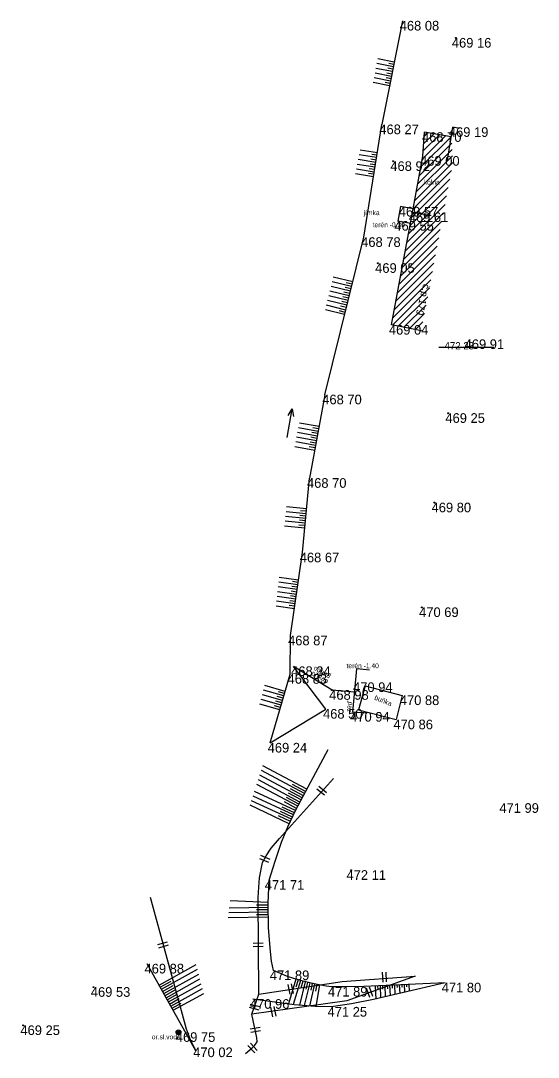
# Model space of a CAD drawing. Extents: x -553731 to -553573, y -1076100 to -1075378.
# Drawn here: x -553641.9 to -553588.3, y -1075774 to -1075666.6 of the extents above; entities that cross this region are included whole.
import ezdxf

# ---------------------------------------------------------------- set-up
doc = ezdxf.new("R2010")
doc.units = 0
for name, color, linetype in [('1', 7, 'Continuous'), ('14', 7, 'Continuous'), ('18', 7, 'Continuous'), ('26', 7, 'Continuous'), ('27', 7, 'Continuous'), ('28', 7, 'Continuous'), ('32', 7, 'Continuous'), ('52', 7, 'Continuous'), ('54_C_POPISNA', 7, 'Continuous'), ('6', 7, 'Continuous'), ('62', 7, 'Continuous')]:
    doc.layers.add(name, color=color, linetype=linetype)

# ---------------------------------------------------------------- blocks, each defined once
blk = doc.blocks.new('POINT_DISPLAY')
blk.add_line((0, 0), (0, 0))
blk = doc.blocks.new('T')
at = {"layer": '6'}
blk.add_circle((0, 0), 0.05, dxfattribs=at)
blk = doc.blocks.new('VOTOK')
at = {"layer": '28'}
for p, q in [((-3.001, 0.001), (0, 0)), ((-0.751, 0.282), (0, 0)), ((0, 0), (-0.751, -0.281))]:
    blk.add_line(p, q, dxfattribs=at)
blk = doc.blocks.new('ROV')
at = {"layer": '62'}
for p, q in [((-0.348, -0.51), (-0.348, 0.51)), ((0, -0.51), (0, 0.51))]:
    blk.add_line(p, q, dxfattribs=at)
blk = doc.blocks.new('OSV')
at = {"layer": '1'}
for radius in [0.25, 0.158, 0.05]:
    blk.add_circle((0, 0), radius, dxfattribs=at)

msp = doc.modelspace()

# ---------------------------------------------------------------- linework, layer by layer
at = {"layer": '14'}
for p, q in [((-553600.25, -1075680.66), (-553600.07, -1075678.19)), ((-553597.31, -1075678.65), (-553600.07, -1075678.19)), ((-553597.71, -1075681.08), (-553597.15, -1075677.67)), ((-553596.45, -1075677.79), (-553597.15, -1075677.67)), ((-553601.31, -1075686.49), (-553600.25, -1075680.66)), ((-553603.49, -1075698.16), (-553601.31, -1075686.49)), ((-553599.38, -1075686.85), (-553601.31, -1075686.49)), ((-553600.41, -1075698.75), (-553603.49, -1075698.16))]:
    msp.add_line(p, q, dxfattribs=at)
at = {"layer": '18'}
for p, q in [((-553602.57, -1075685.9), (-553602.85, -1075687.4)), ((-553601.25, -1075686.14), (-553602.57, -1075685.9)), ((-553601.53, -1075687.65), (-553602.85, -1075687.4)), ((-553607.52, -1075738.26), (-553607.08, -1075733.8)), ((-553605.79, -1075733.92), (-553607.08, -1075733.8)), ((-553606.24, -1075735.54), (-553606.9, -1075738.05)), ((-553606.24, -1075735.54), (-553602.38, -1075736.54)), ((-553602.38, -1075736.54), (-553603.03, -1075739.05)), ((-553606.15, -1075738.39), (-553607.52, -1075738.26)), ((-553606.9, -1075738.05), (-553603.03, -1075739.05))]:
    msp.add_line(p, q, dxfattribs=at)
at = {"layer": '26'}
for p, q in [((-553603.22, -1075670.93), (-553604.92, -1075670.59)), ((-553603.41, -1075671.91), (-553605.11, -1075671.58)), ((-553603.31, -1075671.42), (-553605.01, -1075671.08)), ((-553603.36, -1075671.67), (-553603.87, -1075671.56)), ((-553603.26, -1075671.18), (-553603.77, -1075671.07)), ((-553603.6, -1075672.89), (-553605.3, -1075672.56)), ((-553603.51, -1075672.4), (-553605.2, -1075672.07)), ((-553603.55, -1075672.65), (-553604.06, -1075672.55)), ((-553603.46, -1075672.16), (-553603.97, -1075672.06)), ((-553603.7, -1075673.38), (-553605.4, -1075673.05)), ((-553603.65, -1075673.14), (-553604.16, -1075673.04)), ((-553604.96, -1075680.33), (-553606.76, -1075680.04)), ((-553605.12, -1075681.32), (-553606.95, -1075681.02)), ((-553605.04, -1075680.82), (-553606.85, -1075680.53)), ((-553605.08, -1075681.07), (-553605.63, -1075680.98)), ((-553605, -1075680.58), (-553605.54, -1075680.49)), ((-553605.36, -1075682.8), (-553607.24, -1075682.5)), ((-553605.28, -1075682.31), (-553607.14, -1075682.01)), ((-553605.2, -1075681.81), (-553607.05, -1075681.52)), ((-553605.32, -1075682.55), (-553605.88, -1075682.46)), ((-553605.24, -1075682.06), (-553605.8, -1075681.97)), ((-553605.16, -1075681.56), (-553605.71, -1075681.48)), ((-553607.51, -1075693.69), (-553609.53, -1075693.2)), ((-553607.75, -1075694.67), (-553609.76, -1075694.17)), ((-553607.63, -1075694.18), (-553609.64, -1075693.68)), ((-553607.69, -1075694.42), (-553608.3, -1075694.27)), ((-553607.57, -1075693.94), (-553608.18, -1075693.79)), ((-553607.99, -1075695.64), (-553610, -1075695.14)), ((-553607.87, -1075695.15), (-553609.88, -1075694.65)), ((-553607.93, -1075695.39), (-553608.53, -1075695.24)), ((-553607.81, -1075694.91), (-553608.42, -1075694.76)), ((-553608.23, -1075696.61), (-553610.23, -1075696.11)), ((-553608.11, -1075696.12), (-553610.12, -1075695.63)), ((-553608.17, -1075696.36), (-553608.77, -1075696.22)), ((-553608.05, -1075695.88), (-553608.65, -1075695.73)), ((-553608.35, -1075697.09), (-553610.35, -1075696.6)), ((-553608.29, -1075696.85), (-553608.89, -1075696.7)), ((-553611.18, -1075709.67), (-553613.22, -1075709.3)), ((-553611.09, -1075709.18), (-553613.12, -1075708.81)), ((-553611, -1075708.69), (-553613.03, -1075708.32)), ((-553611.14, -1075709.42), (-553611.75, -1075709.31)), ((-553611.05, -1075708.93), (-553611.66, -1075708.82)), ((-553611.36, -1075710.65), (-553613.41, -1075710.28)), ((-553611.27, -1075710.16), (-553613.32, -1075709.79)), ((-553611.32, -1075710.41), (-553611.93, -1075710.3)), ((-553611.23, -1075709.92), (-553611.84, -1075709.8)), ((-553611.45, -1075711.15), (-553613.51, -1075710.77)), ((-553611.41, -1075710.9), (-553612.02, -1075710.79)), ((-553612.33, -1075717.71), (-553614.41, -1075717.51)), ((-553612.29, -1075717.21), (-553614.36, -1075717.01)), ((-553612.36, -1075717.96), (-553612.98, -1075717.9)), ((-553612.31, -1075717.46), (-553612.93, -1075717.4)), ((-553612.47, -1075719.2), (-553614.57, -1075719)), ((-553612.43, -1075718.7), (-553614.52, -1075718.5)), ((-553612.38, -1075718.2), (-553614.47, -1075718)), ((-553612.45, -1075718.95), (-553613.08, -1075718.89)), ((-553612.4, -1075718.45), (-553613.03, -1075718.39)), ((-553613.12, -1075724.59), (-553615.13, -1075724.31)), ((-553613.26, -1075725.58), (-553615.23, -1075725.3)), ((-553613.19, -1075725.08), (-553615.18, -1075724.8)), ((-553613.23, -1075725.33), (-553613.82, -1075725.25)), ((-553613.16, -1075724.84), (-553613.76, -1075724.75)), ((-553613.4, -1075726.57), (-553615.34, -1075726.3)), ((-553613.33, -1075726.07), (-553615.29, -1075725.8)), ((-553613.37, -1075726.32), (-553613.95, -1075726.24)), ((-553613.3, -1075725.83), (-553613.89, -1075725.74)), ((-553613.54, -1075727.56), (-553615.44, -1075727.29)), ((-553613.47, -1075727.06), (-553615.39, -1075726.79)), ((-553613.51, -1075727.31), (-553614.08, -1075727.23)), ((-553613.44, -1075726.82), (-553614.02, -1075726.74)), ((-553614.65, -1075736.6), (-553616.74, -1075735.99)), ((-553614.51, -1075736.12), (-553616.6, -1075735.51)), ((-553614.58, -1075736.36), (-553615.2, -1075736.18)), ((-553614.92, -1075737.56), (-553617.01, -1075736.96)), ((-553614.78, -1075737.08), (-553616.87, -1075736.48)), ((-553614.85, -1075737.32), (-553615.48, -1075737.14)), ((-553614.72, -1075736.84), (-553615.34, -1075736.66)), ((-553615.06, -1075738.04), (-553617.14, -1075737.44)), ((-553614.99, -1075737.8), (-553615.62, -1075737.62)), ((-553612.74, -1075747.15), (-553617.13, -1075744.81)), ((-553612.51, -1075746.71), (-553616.97, -1075744.33)), ((-553612.27, -1075746.26), (-553616.82, -1075743.84)), ((-553613.21, -1075748.03), (-553617.44, -1075745.78)), ((-553612.98, -1075747.59), (-553617.28, -1075745.3)), ((-553612.39, -1075746.49), (-553613.74, -1075745.77)), ((-553613.44, -1075748.47), (-553617.67, -1075746.49)), ((-553612.86, -1075747.37), (-553614.16, -1075746.67)), ((-553612.62, -1075746.93), (-553613.95, -1075746.22)), ((-553614.08, -1075749.83), (-553618.13, -1075747.93)), ((-553613.87, -1075749.38), (-553617.98, -1075747.45)), ((-553613.66, -1075748.93), (-553617.82, -1075746.97)), ((-553613.33, -1075748.25), (-553614.59, -1075747.58)), ((-553613.09, -1075747.81), (-553614.37, -1075747.13)), ((-553613.97, -1075749.6), (-553615.2, -1075749.03)), ((-553613.76, -1075749.15), (-553615, -1075748.57)), ((-553613.55, -1075748.7), (-553614.81, -1075748.11)), ((-553616.25, -1075758.51), (-553620.3, -1075758.57)), ((-553616.26, -1075758.01), (-553620.22, -1075757.82)), ((-553616.25, -1075758.76), (-553617.47, -1075758.77)), ((-553616.26, -1075758.26), (-553617.46, -1075758.27)), ((-553616.24, -1075759.51), (-553620.4, -1075759.57)), ((-553616.24, -1075759.01), (-553620.35, -1075759.07)), ((-553616.24, -1075759.26), (-553617.48, -1075759.28)), ((-553627.56, -1075766.55), (-553623.73, -1075764.42)), ((-553627.32, -1075766.99), (-553623.59, -1075764.92)), ((-553627.44, -1075766.77), (-553626.31, -1075766.14)), ((-553627.07, -1075767.43), (-553623.46, -1075765.42)), ((-553626.83, -1075767.86), (-553623.33, -1075765.92)), ((-553613.4, -1075765.93), (-553614.17, -1075768.51)), ((-553612.92, -1075766.07), (-553613.67, -1075768.58)), ((-553613.16, -1075766), (-553613.39, -1075766.77)), ((-553612.44, -1075766.21), (-553613.04, -1075768.64)), ((-553612.68, -1075766.15), (-553612.9, -1075766.88)), ((-553612.19, -1075766.27), (-553612.37, -1075766.99)), ((-553627.2, -1075767.21), (-553626.1, -1075766.6)), ((-553626.95, -1075767.64), (-553625.89, -1075767.05)), ((-553626.59, -1075768.3), (-553623.2, -1075766.42)), ((-553626.35, -1075768.74), (-553623.07, -1075766.92)), ((-553611.95, -1075766.33), (-553612.54, -1075768.68)), ((-553611.46, -1075766.44), (-553611.98, -1075768.73)), ((-553611.71, -1075766.39), (-553611.86, -1075767.08)), ((-553611.22, -1075766.5), (-553611.37, -1075767.17)), ((-553610.97, -1075766.54), (-553611.34, -1075768.78)), ((-553605.19, -1075766.65), (-553605.12, -1075768)), ((-553604.94, -1075766.64), (-553604.92, -1075767.03)), ((-553604.69, -1075766.62), (-553604.63, -1075767.88)), ((-553604.44, -1075766.61), (-553604.42, -1075766.98)), ((-553604.19, -1075766.6), (-553604.14, -1075767.77)), ((-553603.94, -1075766.59), (-553603.92, -1075766.93)), ((-553603.69, -1075766.58), (-553603.64, -1075767.65)), ((-553603.44, -1075766.57), (-553603.43, -1075766.88)), ((-553603.19, -1075766.56), (-553603.14, -1075767.54)), ((-553602.94, -1075766.54), (-553602.93, -1075766.82)), ((-553602.69, -1075766.53), (-553602.65, -1075767.42)), ((-553602.44, -1075766.52), (-553602.43, -1075766.77)), ((-553602.19, -1075766.51), (-553602.15, -1075767.3)), ((-553601.94, -1075766.5), (-553601.93, -1075766.72)), ((-553601.69, -1075766.49), (-553601.66, -1075767.19)), ((-553626.71, -1075768.08), (-553625.68, -1075767.51)), ((-553626.47, -1075768.52), (-553625.47, -1075767.96)), ((-553626.22, -1075768.96), (-553625.26, -1075768.42)), ((-553626.1, -1075769.17), (-553622.94, -1075767.42))]:
    msp.add_line(p, q, dxfattribs=at)
at = {"layer": '27'}
for p, q in [((-553602.37, -1075666.65), (-553604.49, -1075677.39)), ((-553606.37, -1075689.07), (-553604.49, -1075677.39)), ((-553610.4, -1075705.38), (-553606.37, -1075689.07)), ((-553610.4, -1075705.38), (-553611.98, -1075714.03)), ((-553612.72, -1075721.75), (-553611.98, -1075714.03)), ((-553613.94, -1075730.35), (-553612.72, -1075721.75)), ((-553613.99, -1075734.33), (-553613.94, -1075730.35)), ((-553610.31, -1075737.95), (-553613.63, -1075733.53)), ((-553609.66, -1075735.99), (-553613.63, -1075733.53)), ((-553616.05, -1075741.46), (-553613.99, -1075734.33)), ((-553607.32, -1075736.22), (-553609.66, -1075735.99)), ((-553616.05, -1075741.46), (-553610.31, -1075737.95)), ((-553623.77, -1075773.38), (-553628.78, -1075764.35))]:
    msp.add_line(p, q, dxfattribs=at)
for points in [[(-553616.15, -1075755.68), (-553615.56, -1075753.71), (-553614.89, -1075751.75), (-553614.24, -1075750.17), (-553613.4, -1075748.38), (-553610.07, -1075742.13)], [(-553615.72, -1075765.04), (-553615.92, -1075764.09), (-553616.04, -1075763.09), (-553616.22, -1075760.63), (-553616.26, -1075758.07), (-553616.15, -1075755.68)], [(-553609.7, -1075766.74), (-553610.28, -1075766.65), (-553611.15, -1075766.51), (-553611.8, -1075766.36), (-553612.66, -1075766.15), (-553613.62, -1075765.86), (-553614.28, -1075765.65), (-553615.72, -1075765.04)], [(-553597.93, -1075766.31), (-553605.36, -1075768.06), (-553607.63, -1075768.5), (-553609.75, -1075768.82)], [(-553597.93, -1075766.31), (-553606.36, -1075766.7), (-553608.37, -1075766.75), (-553609.7, -1075766.74)], [(-553609.75, -1075768.82), (-553611.4, -1075768.77), (-553613.57, -1075768.59), (-553617.87, -1075768.01)]]:
    msp.add_lwpolyline(points, dxfattribs=at)
at = {"layer": '32'}
for p, q in [((-553600.46, -1075681.79), (-553597.31, -1075678.65)), ((-553600.3, -1075680.93), (-553597.92, -1075678.55)), ((-553600.21, -1075680.13), (-553598.53, -1075678.45)), ((-553600.16, -1075679.37), (-553599.13, -1075678.34)), ((-553600.1, -1075678.61), (-553599.74, -1075678.25)), ((-553600.77, -1075683.52), (-553597.23, -1075679.98)), ((-553600.61, -1075682.66), (-553597.27, -1075679.31)), ((-553601.08, -1075685.25), (-553597.15, -1075681.31)), ((-553600.93, -1075684.38), (-553597.19, -1075680.64)), ((-553601.24, -1075686.11), (-553597.3, -1075682.17)), ((-553601.4, -1075686.98), (-553597.46, -1075683.04)), ((-553601.56, -1075687.85), (-553597.63, -1075683.91)), ((-553601.89, -1075689.59), (-553597.96, -1075685.66)), ((-553601.73, -1075688.72), (-553597.79, -1075684.78)), ((-553602.05, -1075690.46), (-553598.12, -1075686.53)), ((-553602.21, -1075691.33), (-553598.28, -1075687.4)), ((-553602.38, -1075692.2), (-553598.45, -1075688.27)), ((-553602.7, -1075693.94), (-553598.77, -1075690.01)), ((-553602.54, -1075693.07), (-553598.61, -1075689.14)), ((-553602.86, -1075694.81), (-553598.94, -1075690.88)), ((-553603.03, -1075695.67), (-553599.1, -1075691.75)), ((-553603.19, -1075696.54), (-553599.26, -1075692.62)), ((-553603.35, -1075697.41), (-553599.43, -1075693.49)), ((-553603.41, -1075698.18), (-553599.59, -1075694.36)), ((-553602.81, -1075698.29), (-553599.75, -1075695.23)), ((-553602.22, -1075698.4), (-553599.92, -1075696.1)), ((-553601.62, -1075698.52), (-553600.08, -1075696.97)), ((-553601.03, -1075698.63), (-553600.24, -1075697.84)), ((-553600.44, -1075698.74), (-553600.41, -1075698.71))]:
    msp.add_line(p, q, dxfattribs=at)
at = {"layer": '62'}
for p, q in [((-553598.61, -1075700.47), (-553592.92, -1075700.47)), ((-553615.1, -1075751.35), (-553609.5, -1075745.14)), ((-553615.95, -1075752.38), (-553615.1, -1075751.35)), ((-553616.84, -1075753.87), (-553616.46, -1075753.17)), ((-553616.46, -1075753.17), (-553615.95, -1075752.38)), ((-553617.16, -1075755.44), (-553616.84, -1075753.87)), ((-553617.24, -1075756.4), (-553617.16, -1075755.44)), ((-553617.3, -1075757.5), (-553617.24, -1075756.4)), ((-553624.72, -1075771.13), (-553628.45, -1075757.49)), ((-553617.25, -1075767.5), (-553617.3, -1075757.5)), ((-553617.25, -1075767.5), (-553608.6, -1075766.2)), ((-553608.6, -1075766.2), (-553601.05, -1075765.62)), ((-553601.05, -1075765.62), (-553608.12, -1075768.18)), ((-553617.95, -1075769.56), (-553617.25, -1075767.5)), ((-553608.12, -1075768.18), (-553617.95, -1075769.56)), ((-553617.44, -1075772.03), (-553617.95, -1075769.56)), ((-553624.32, -1075772.24), (-553624.72, -1075771.13)), ((-553623.77, -1075773.38), (-553624.32, -1075772.24)), ((-553617.64, -1075772.78), (-553617.4, -1075772.45)), ((-553617.4, -1075772.45), (-553617.44, -1075772.03)), ((-553618.6, -1075773.63), (-553617.91, -1075773.06)), ((-553617.91, -1075773.06), (-553617.64, -1075772.78))]:
    msp.add_line(p, q, dxfattribs=at)

# ---------------------------------------------------------------- block references
at = {"layer": '1'}
for name, p in [('POINT_DISPLAY', (-553602.37, -1075666.65)), ('POINT_DISPLAY', (-553596.84, -1075668.42)), ('POINT_DISPLAY', (-553604.49, -1075677.39)), ('POINT_DISPLAY', (-553600.07, -1075678.19)), ('POINT_DISPLAY', (-553597.15, -1075677.67)), ('POINT_DISPLAY', (-553603.33, -1075681.2)), ('POINT_DISPLAY', (-553600.25, -1075680.66)), ('POINT_DISPLAY', (-553602.47, -1075685.92)), ('POINT_DISPLAY', (-553601.31, -1075686.49)), ('POINT_DISPLAY', (-553602.92, -1075687.39)), ('POINT_DISPLAY', (-553606.37, -1075689.07)), ('POINT_DISPLAY', (-553604.9, -1075691.76)), ('POINT_DISPLAY', (-553603.49, -1075698.16)), ('POINT_DISPLAY', (-553595.53, -1075699.65)), ('POINT_DISPLAY', (-553610.4, -1075705.38)), ('POINT_DISPLAY', (-553597.63, -1075707.3)), ('POINT_DISPLAY', (-553611.98, -1075714.03)), ('POINT_DISPLAY', (-553599.06, -1075716.57)), ('POINT_DISPLAY', (-553612.72, -1075721.75)), ('POINT_DISPLAY', (-553600.35, -1075727.42)), ('POINT_DISPLAY', (-553613.94, -1075730.35)), ('POINT_DISPLAY', (-553613.63, -1075733.53)), ('POINT_DISPLAY', (-553613.99, -1075734.33)), ('POINT_DISPLAY', (-553609.66, -1075735.99)), ('POINT_DISPLAY', (-553607.22, -1075735.19)), ('POINT_DISPLAY', (-553602.38, -1075736.54)), ('POINT_DISPLAY', (-553610.31, -1075737.95)), ('POINT_DISPLAY', (-553607.52, -1075738.26)), ('POINT_DISPLAY', (-553603.03, -1075739.05)), ('POINT_DISPLAY', (-553616.05, -1075741.46)), ('POINT_DISPLAY', (-553591.94, -1075747.71)), ('POINT_DISPLAY', (-553607.68, -1075754.65)), ('POINT_DISPLAY', (-553616.15, -1075755.68)), ('POINT_DISPLAY', (-553628.78, -1075764.35)), ('POINT_DISPLAY', (-553615.72, -1075765.04)), ('POINT_DISPLAY', (-553634.34, -1075766.77)), ('POINT_DISPLAY', (-553609.7, -1075766.74)), ('POINT_DISPLAY', (-553597.93, -1075766.31)), ('POINT_DISPLAY', (-553617.87, -1075768.01)), ('POINT_DISPLAY', (-553609.75, -1075768.82)), ('POINT_DISPLAY', (-553641.63, -1075770.73)), ('OSV', (-553625.55, -1075771.44)), ('POINT_DISPLAY', (-553625.55, -1075771.44)), ('POINT_DISPLAY', (-553623.77, -1075773.02))]:
    msp.add_blockref(name, p, dxfattribs=at)
at = {"layer": '28', "xscale": 0.9999996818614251, "yscale": 0.9999996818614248, "rotation": 79.5484867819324}
msp.add_blockref('VOTOK', (-553613.77, -1075706.85), dxfattribs=at)
at = {"layer": '32'}
msp.add_blockref('POINT_DISPLAY', (-553597.31, -1075678.65), dxfattribs=at)
at = {"layer": '6'}
for p in [(-553596.84, -1075668.42), (-553603.33, -1075681.2), (-553604.9, -1075691.76), (-553597.63, -1075707.3), (-553599.06, -1075716.57), (-553600.35, -1075727.42), (-553609.66, -1075735.99), (-553607.68, -1075754.65), (-553634.34, -1075766.77), (-553641.63, -1075770.73)]:
    msp.add_blockref('T', p, dxfattribs=at)
at = {"layer": '62'}
for p, xscale, yscale, rotation in [((-553610.84, -1075746.54), 0.9999979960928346, 0.9999979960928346, -128.80422962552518), ((-553616.71, -1075753.62), 0.9999981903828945, 0.9999981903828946, -112.55217850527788), ((-553627.09, -1075762.54), 0.9999993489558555, 0.9999993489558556, -73.76464016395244), ((-553617.31, -1075762.54), 1.000001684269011, 1.0000016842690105, -89.41061897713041), ((-553604.42, -1075765.73), 0.9999959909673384, 0.9999959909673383, -176.63551342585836), ((-553614.13, -1075767), 0.9999981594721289, 0.9999981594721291, -169.41740186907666), ((-553605.96, -1075767.33), 0.9999972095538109, 0.999997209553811, -159.72831098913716), ((-553617.73, -1075768.99), 0.9999981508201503, 0.9999981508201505, -104.81149015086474), ((-553615.92, -1075769.33), 0.9999981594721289, 0.9999981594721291, -169.41740186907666), ((-553617.56, -1075771.35), 0.9999992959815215, 0.9999992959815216, -80.61430552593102), ((-553618.01, -1075773.19), 1.0000008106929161, 1.0000008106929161, -136.5051081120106)]:
    msp.add_blockref('ROV', p, dxfattribs=dict(at, xscale=xscale, yscale=yscale, rotation=rotation))

# ---------------------------------------------------------------- texts
at = {"layer": '52'}
for s, p in [('kolna', (-553600.16, -1075683.61)), ('jímka', (-553606.38, -1075686.78)), ('terén -0.30', (-553605.45, -1075688.03)), ('terén -1.40', (-553608.15, -1075733.72)), ('or.sl.voda', (-553628.32, -1075772.17))]:
    msp.add_text(s, height=0.5, dxfattribs=at).set_placement(p)
for s, rotation, p in [('příkop', 330.3798, (-553611.85, -1075734.38)), ('odpad', 330.3798, (-553611.62, -1075733.84)), ('zeď', 81.6561, (-553607.75, -1075738.31)), ('buňka', 337.8839, (-553605.32, -1075736.95))]:
    msp.add_text(s, height=0.5, rotation=rotation, dxfattribs=at).set_placement(p)
at = {"layer": '54_C_POPISNA'}
msp.add_text('č.p.179', height=0.75, rotation=256.4353, dxfattribs=at).set_placement((-553600.21, -1075693.85))
at = {"layer": '6'}
for s, p in [('468 08 ', (-553602.65, -1075667.65)), ('469 16 ', (-553597.25, -1075669.42)), ('468 27 ', (-553604.76, -1075678.39)), ('468 70 ', (-553600.34, -1075679.19)), ('469 19 ', (-553597.56, -1075678.67)), ('468 92 ', (-553603.62, -1075682.2)), ('469 00 ', (-553600.54, -1075681.66)), ('469 57 ', (-553602.75, -1075686.92)), ('469 61 ', (-553601.71, -1075687.49)), ('469 55 ', (-553603.21, -1075688.39)), ('468 78 ', (-553606.64, -1075690.07)), ('469 05 ', (-553605.19, -1075692.76)), ('469 04 ', (-553603.77, -1075699.16)), ('469 91 ', (-553595.93, -1075700.65)), ('468 70 ', (-553610.67, -1075706.38)), ('469 25 ', (-553597.92, -1075708.3)), ('468 70 ', (-553612.25, -1075715.03)), ('469 80 ', (-553599.35, -1075717.57)), ('468 67 ', (-553613, -1075722.75)), ('470 69 ', (-553600.64, -1075728.42)), ('468 87 ', (-553614.21, -1075731.35)), ('468 34 ', (-553613.89, -1075734.53)), ('468 83 ', (-553614.26, -1075735.33)), ('468 98 ', (-553609.95, -1075736.99)), ('470 94 ', (-553607.48, -1075736.19)), ('470 88 ', (-553602.64, -1075737.54)), ('468 50 ', (-553610.59, -1075738.95)), ('470 94 ', (-553607.78, -1075739.26)), ('470 86 ', (-553603.3, -1075740.05)), ('469 24 ', (-553616.32, -1075742.46)), ('471 99 ', (-553592.33, -1075748.71)), ('472 11 ', (-553608.16, -1075755.65)), ('471 71 ', (-553616.62, -1075756.68)), ('469 88 ', (-553629.07, -1075765.35)), ('471 89 ', (-553616.1, -1075766.04)), ('469 53 ', (-553634.63, -1075767.77)), ('471 89 ', (-553610.08, -1075767.74)), ('471 80 ', (-553598.3, -1075767.31)), ('470 96 ', (-553618.16, -1075769.01)), ('471 25 ', (-553610.12, -1075769.82)), ('469 25 ', (-553641.92, -1075771.73)), ('469 75 ', (-553625.83, -1075772.44)), ('470 02 ', (-553624.03, -1075774.02))]:
    msp.add_text(s, height=1, dxfattribs=at).set_placement(p)
at = {"layer": '62'}
msp.add_text('472 23', height=0.75, dxfattribs=at).set_placement((-553598.01, -1075700.69))

doc.saveas('drawing.dxf')
